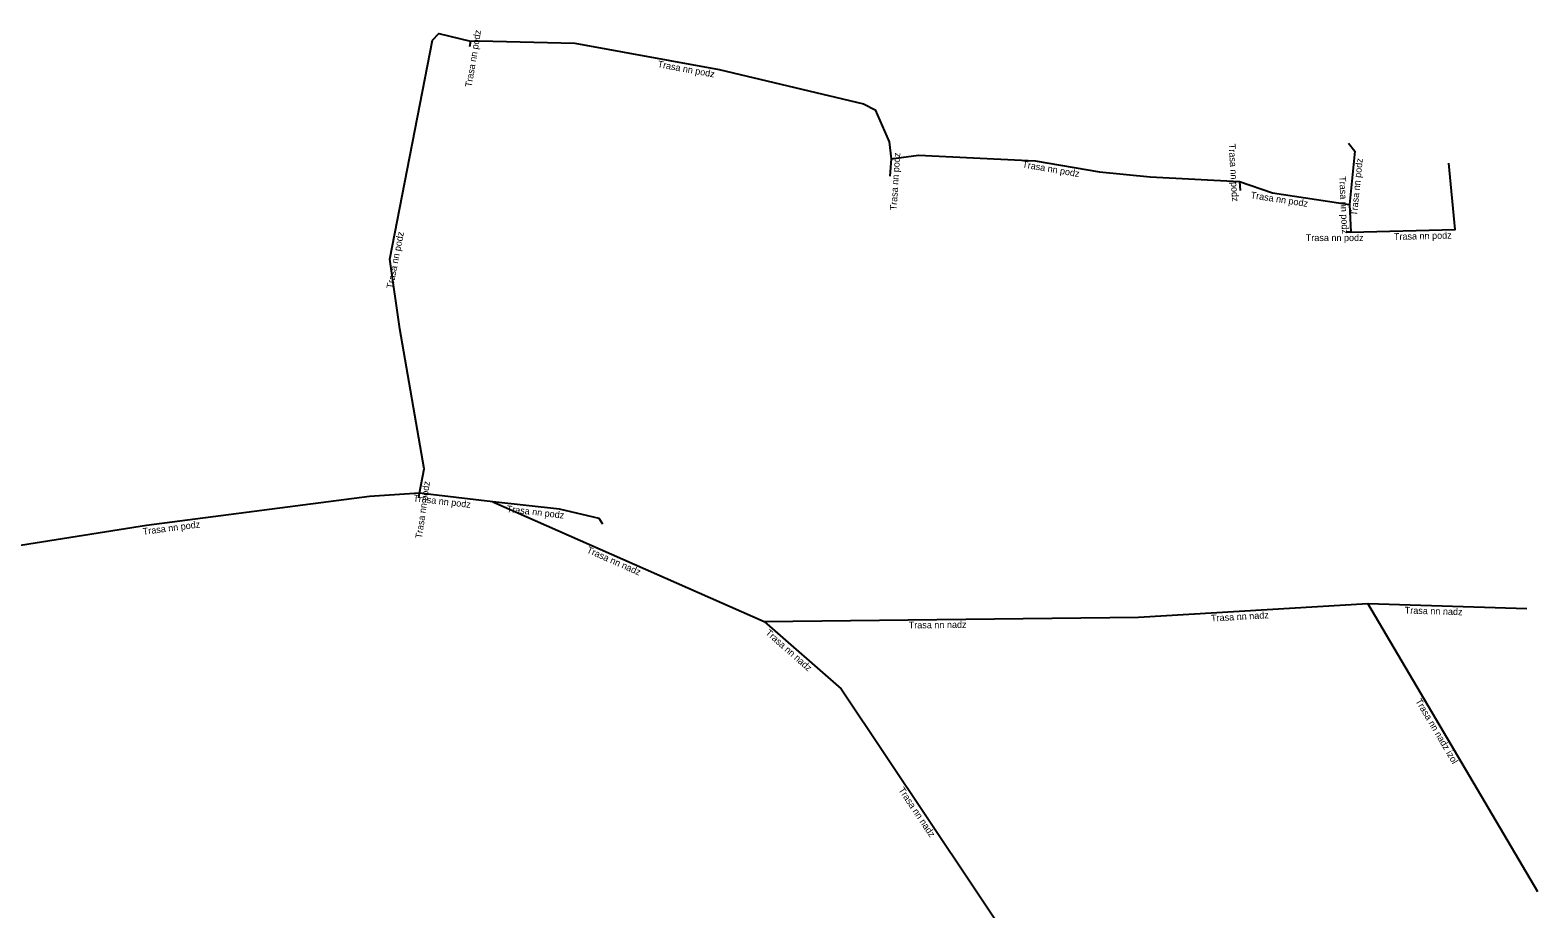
# Model space of a CAD drawing. Extents: x -682605 to -681812, y -1059958 to -1059650.
# Drawn here: x -682001.8 to -681890.3, y -1059781 to -1059716 of the extents above; entities that cross this region are included whole.
import ezdxf

# ---------------------------------------------------------------- set-up
doc = ezdxf.new("R2010")
doc.units = 0
doc.layers.add('Popiskový text - Ostatní atributy Trasy', color=7, linetype='Continuous')
doc.layers.add('Spojnice NN', color=7, linetype='Continuous')

msp = doc.modelspace()

# ---------------------------------------------------------------- linework, layer by layer
at = {"layer": 'Spojnice NN'}
for points in [[(-681973.04, -1059750.26), (-681972.7, -1059748.45), (-681974.51, -1059738.12), (-681975.24, -1059732.95), (-681972.09, -1059716.76), (-681971.62, -1059716.28), (-681969.28, -1059716.84)], [(-681969.28, -1059716.84), (-681969.35, -1059717.26)], [(-681969.28, -1059716.84), (-681968.64, -1059716.81), (-681961.57, -1059716.99), (-681950.88, -1059718.94), (-681940.22, -1059721.48), (-681939.36, -1059721.92), (-681938.31, -1059724.29), (-681938.18, -1059725.54)], [(-681904.34, -1059724.38), (-681903.89, -1059724.96), (-681904.29, -1059728.92)], [(-681938.18, -1059725.54), (-681938.26, -1059726.82)], [(-681938.18, -1059725.54), (-681936.14, -1059725.26), (-681927.51, -1059725.68), (-681922.76, -1059726.49), (-681919.03, -1059726.86), (-681912.4, -1059727.21)], [(-681904.19, -1059730.97), (-681896.46, -1059730.77), (-681896.93, -1059725.87)], [(-681912.4, -1059727.21), (-681909.96, -1059728.05), (-681904.29, -1059728.92)], [(-681912.4, -1059727.21), (-681912.36, -1059727.87)], [(-681904.29, -1059728.92), (-681904.19, -1059730.97)], [(-681904.19, -1059730.97), (-681904.53, -1059730.97)], [(-681973.04, -1059750.26), (-681976.75, -1059750.5), (-681993.23, -1059752.66), (-682006.15, -1059754.71), (-682006.44, -1059755.34), (-682006.62, -1059755.81), (-682006.45, -1059756.21)], [(-681973.09, -1059750.61), (-681973.04, -1059750.26)], [(-681967.62, -1059750.89), (-681973.04, -1059750.26)], [(-681959.5, -1059752.55), (-681959.77, -1059752.14), (-681962.7, -1059751.45), (-681967.62, -1059750.89)], [(-681967.62, -1059750.89), (-681947.56, -1059759.74)], [(-681919.89, -1059759.43), (-681902.91, -1059758.43)], [(-681902.91, -1059758.43), (-681891.16, -1059758.79)], [(-681890.35, -1059779.73), (-681902.91, -1059758.43)], [(-681947.56, -1059759.74), (-681919.89, -1059759.43)], [(-681947.56, -1059759.74), (-681941.87, -1059764.74)], [(-681941.87, -1059764.74), (-681928.86, -1059784.2)]]:
    msp.add_lwpolyline(points, dxfattribs=at)

# ---------------------------------------------------------------- texts
at = {"layer": 'Popiskový text - Ostatní atributy Trasy'}
for s, rotation, p in [('Trasa nn podz', 80.5377, (-681969.19, -1059720.26)), ('Trasa nn podz', 349.6621, (-681955.47, -1059718.76)), ('Trasa nn podz', 273.3614, (-681913.21, -1059724.44)), ('Trasa nn podz', 86.2812, (-681937.77, -1059729.36)), ('Trasa nn podz', 350.2677, (-681928.5, -1059726.17)), ('Trasa nn podz', 84.2321, (-681903.72, -1059729.77)), ('Trasa nn podz', 272.7927, (-681905.04, -1059726.83)), ('Trasa nn podz', 351.2766, (-681911.61, -1059728.45)), ('Trasa nn podz', 78.9898, (-681975.01, -1059735.17)), ('Trasa nn podz', 1.4821, (-681900.99, -1059731.54)), ('Trasa nn podz', 81.8699, (-681972.87, -1059753.64)), ('Trasa nn podz', 353.3699, (-681973.53, -1059750.86)), ('Trasa nn podz', 353.5065, (-681966.62, -1059751.66)), ('Trasa nn podz', 7.4671, (-681993.48, -1059753.35)), ('Trasa nn nadz', 336.1941, (-681960.73, -1059754.64)), ('Trasa nn nadz', 3.3704, (-681914.5, -1059759.76)), ('Trasa nn nadz', 358.2602, (-681900.2, -1059759.16)), ('Trasa nn nadz', 318.6788, (-681947.51, -1059760.65)), ('Trasa nn nadz', 0.6419, (-681936.87, -1059760.27)), ('Trasa nn nadz izol', 300.5283, (-681899.42, -1059765.63)), ('Trasa nn nadz', 303.7756, (-681937.66, -1059772.21))]:
    msp.add_text(s, height=0.5, rotation=rotation, dxfattribs=at).set_placement(p)
msp.add_text('Trasa nn podz', height=0.5, dxfattribs=at).set_placement((-681907.51, -1059731.62))

doc.saveas('drawing.dxf')
